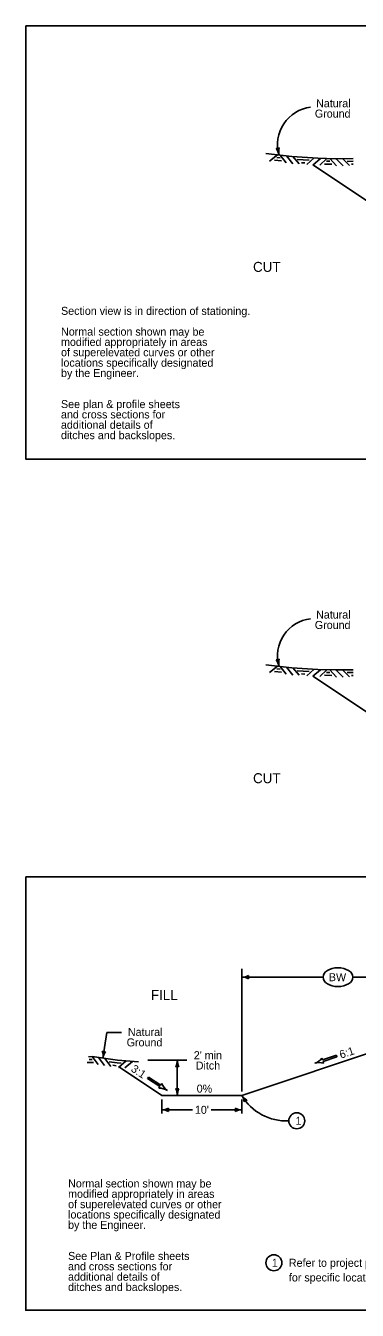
# Model space of a CAD drawing. Extents: x 4574 to 81668, y 5908 to 13780.
# Drawn here: x 10148 to 10645, y 5908 to 7834 of the extents above; entities that cross this region are included whole.
import ezdxf

# ---------------------------------------------------------------- set-up
doc = ezdxf.new("R2010")
doc.units = 0
for name, color, linetype in [('Cell', 7, 'Continuous'), ('dsnStdBorder', 7, 'Continuous'), ('dsnStdLabel', 7, 'Continuous'), ('dsnStdNote', 7, 'Continuous'), ('dsnTextFinalPlan', 7, 'Continuous'), ('dsnXsExistingGround', 7, 'Continuous')]:
    doc.layers.add(name, color=color, linetype=linetype)

msp = doc.modelspace()

# ---------------------------------------------------------------- linework, layer by layer
at = {"layer": 'Cell'}
for p, q in [((10757.5, 7505.6), (10577.8, 7625.3)), ((10757.5, 6738.7), (10577.8, 6858.5)), ((10780.6, 6332.7), (10471.7, 6229.8)), ((10351.7, 6229.8), (10288.2, 6272.1)), ((10351.7, 6229.8), (10471.7, 6229.8))]:
    msp.add_line(p, q, dxfattribs=at)
at = {"layer": 'dsnStdBorder'}
for points in [[(10147.5, 7834), (13252.5, 7834), (13252.5, 7184), (10147.5, 7184), (10147.5, 7834)], [(10147.5, 6557.5), (13252.5, 6557.5), (13252.5, 5907.5), (10147.5, 5907.5), (10147.5, 6557.5)]]:
    msp.add_lwpolyline(points, dxfattribs=at)
at = {"layer": 'dsnStdLabel'}
for p, q in [((10269.3, 6324.2), (10263.1, 6285.8)), ((10291, 6324.2), (10269.3, 6324.2)), ((10591.7, 6285.8), (10592.6, 6283.2)), ((10592.6, 6283.2), (10613.4, 6290.1)), ((10614.2, 6287.9), (10593.3, 6280.9)), ((10593.3, 6280.9), (10594.2, 6278.3)), ((10613.4, 6290.1), (10614.2, 6287.9)), ((10580.8, 6278), (10580.8, 6278)), ((10331.6, 6257.4), (10330.3, 6255.4)), ((10330.3, 6255.4), (10348.6, 6243.2)), ((10349.9, 6245.2), (10331.6, 6257.4)), ((10348.6, 6243.2), (10347, 6240.8)), ((10351.5, 6247.5), (10349.9, 6245.2)), ((10359.9, 6237.1), (10359.9, 6237.1))]:
    msp.add_line(p, q, dxfattribs=at)
for centre, radius, start, end in [((10581.1, 7656), 56, 96.6165, 196.0565), ((10523.9, 7658), 8.21, 263.2989, 298.7656), ((10506.4, 7636.4), 21.3, 11.0323, 39.1047), ((10548.1, 7644.5), 21.3, 162.9598, 191.0323), ((10581.1, 6889.1), 56, 96.6165, 196.0565), ((10523.9, 6891.1), 8.21, 263.2989, 298.7656), ((10506.4, 6869.6), 21.3, 11.0323, 39.1047), ((10548.1, 6877.7), 21.3, 162.9598, 191.0323), ((10266.1, 6303.3), 8.21, 242.6946, 278.1613), ((10242.2, 6289.3), 21.3, 350.428, 18.5005), ((10284.1, 6282.2), 21.3, 142.3555, 170.428), ((10571.7, 6302.1), 25.8, 290.787, 320.817), ((10588, 6253.2), 25.8, 76.053, 106.083), ((10375.1, 6258), 25.8, 203.9305, 233.9606), ((10346.5, 6215.1), 25.8, 58.6646, 88.6946), ((10537.7, 6267.6), 76, 209.8583, 273.1714), ((10489.4, 6241.5), 21.3, 213.5549, 241.6274), ((10454, 6218), 21.3, 5.4824, 33.5549), ((10481.6, 6214.9), 8.21, 105.8215, 141.2882)]:
    msp.add_arc(centre, radius, start, end, dxfattribs=at)
at = {"layer": 'dsnStdNote'}
for centre in [(10553.9, 6191.7), (10519.6, 5978.8)]:
    msp.add_circle(centre, 12, dxfattribs=at)
at = {"layer": 'dsnTextFinalPlan'}
for p, q in [((10471.7, 6235.8), (10471.7, 6419.7)), ((10593.3, 6407.1), (10471.7, 6407.1)), ((10774.3, 6407.1), (10638.1, 6407.1)), ((10389.3, 6282.6), (10330.5, 6282.6)), ((10374.8, 6229.8), (10374.8, 6282.6)), ((10351.7, 6223.7), (10351.7, 6202.6)), ((10471.7, 6223.7), (10471.7, 6202.6)), ((10351.7, 6208.2), (10397.7, 6208.2)), ((10425.7, 6208.2), (10471.7, 6208.2))]:
    msp.add_line(p, q, dxfattribs=at)
for centre, radius, start, end in [((10471.7, 6428.4), 21.3, 270, 298.0725), ((10471.7, 6385.9), 21.3, 61.9275, 90), ((10489.5, 6407.1), 8.21, 162.2666, 197.7334), ((10353.6, 6282.6), 21.3, 331.9275, 0), ((10396.1, 6282.6), 21.3, 180, 208.0725), ((10374.8, 6264.8), 8.21, 72.2666, 107.7334), ((10374.8, 6247.6), 8.21, 252.2666, 287.7334), ((10353.6, 6229.8), 21.3, 0, 28.0725), ((10396.1, 6229.8), 21.3, 151.9275, 180), ((10351.7, 6229.5), 21.3, 270, 298.0725), ((10351.7, 6187), 21.3, 61.9275, 90), ((10369.5, 6208.2), 8.21, 162.2666, 197.7334), ((10453.9, 6208.2), 8.21, 342.2666, 17.7334), ((10471.7, 6229.5), 21.3, 241.9275, 270), ((10471.7, 6187), 21.3, 90, 118.0725)]:
    msp.add_arc(centre, radius, start, end, dxfattribs=at)
msp.add_ellipse((10615.7, 6407.1), major_axis=(-22.4, 0), ratio=0.628754, dxfattribs=at)
at = {"layer": 'dsnXsExistingGround'}
for p, q in [((10524.8, 7640.4), (10513.1, 7631)), ((10528.8, 7640), (10538.2, 7628.3)), ((10538.5, 7638.8), (10547.9, 7627.1)), ((10547.8, 7638), (10557.6, 7626.7)), ((10580.1, 7635.8), (10568.8, 7625.9)), ((10589.4, 7635), (10578.1, 7625.1)), ((10599.2, 7635), (10588.3, 7624.7)), ((10603.3, 7634.9), (10613.5, 7624)), ((10613, 7634.5), (10623.7, 7623.9)), ((10622.3, 7634.7), (10633, 7624.2)), ((10524.8, 6873.6), (10513.1, 6864.2)), ((10528.8, 6873.1), (10538.2, 6861.5)), ((10538.5, 6871.9), (10547.9, 6860.2)), ((10547.8, 6871.1), (10557.6, 6859.8)), ((10580.1, 6868.9), (10568.8, 6859.1)), ((10589.4, 6868.1), (10578.1, 6858.3)), ((10599.2, 6868.2), (10588.3, 6857.9)), ((10603.3, 6868), (10613.5, 6857.1)), ((10613, 6867.6), (10623.7, 6857.1)), ((10622.3, 6867.8), (10633, 6857.3)), ((10247.1, 6288), (10256.1, 6276)), ((10256.7, 6286.5), (10265.7, 6274.5)), ((10266, 6285.4), (10275, 6273.4)), ((10298.2, 6281.7), (10286.8, 6271.9)), ((10307.5, 6280.9), (10296.1, 6271.1))]:
    msp.add_line(p, q, dxfattribs=at)
for points in [[(10638.6, 7634.8), (10612, 7634.6), (10585.5, 7635.4), (10546.4, 7638.1), (10507.5, 7642.3)], [(10531.2, 7631.2), (10520.6, 7632.3)], [(10528.8, 7635.9), (10523.9, 7636.4)], [(10572.7, 7632.2), (10554.7, 7633.4)], [(10603.6, 7630.8), (10598.7, 7630.9)], [(10638.6, 7630.7), (10629.6, 7630.6)], [(10565.8, 7628.3), (10560.9, 7628.6)], [(10606.3, 7626.3), (10595.7, 7626.6)], [(10638.6, 7626.4), (10636.2, 7626.3)], [(10638.6, 6868), (10612, 6867.8), (10585.5, 6868.6), (10546.4, 6871.2), (10507.5, 6875.4)], [(10531.2, 6864.3), (10520.6, 6865.5)], [(10528.8, 6869), (10523.9, 6869.5)], [(10572.7, 6865.3), (10554.7, 6866.6)], [(10565.8, 6861.4), (10560.9, 6861.8)], [(10606.3, 6859.4), (10595.7, 6859.8)], [(10603.6, 6863.9), (10598.7, 6864.1)], [(10638.6, 6863.9), (10629.6, 6863.8)], [(10638.6, 6859.5), (10636.2, 6859.5)], [(10241.8, 6287.9), (10247.4, 6288), (10285.3, 6282.6), (10316.4, 6280.4)], [(10242.6, 6283.8), (10247.1, 6283.8)], [(10239.8, 6279.4), (10246.9, 6279.4), (10249.1, 6279.1)], [(10272.5, 6280.3), (10284.8, 6278.6), (10290.7, 6278.1)], [(10278.4, 6275.1), (10283.3, 6274.4)]]:
    msp.add_lwpolyline(points, dxfattribs=at)

# ---------------------------------------------------------------- texts
at = {"layer": 'dsnStdLabel'}
for s, p in [('Ground', (10581, 7696.2)), ('Natural', (10582.9, 7711.7)), ('Natural', (10582.9, 6944.9)), ('Ground', (10581, 6929.3)), ('Natural', (10300.8, 6318.9)), ('Ground', (10298.9, 6303.3))]:
    msp.add_text(s, height=12, dxfattribs=at).set_placement(p)
for s, height, rotation, p in [('CUT', 15, 0.0415, (10488.4, 7464.8)), ('CUT', 15, 0.0415, (10488.4, 6698)), ('FILL', 15, 359.9586, (10335.2, 6372.9)), ('6:1', 12, 18.435, (10620.2, 6284.8)), ('3:1', 12, 326.3126, (10304.3, 6266.9))]:
    msp.add_text(s, height=height, rotation=rotation, dxfattribs=at).set_placement(p)
at = {"layer": 'dsnStdNote'}
for s, rotation, p in [('Section view is in direction of stationing.', 359.9583, (10200.5, 7400.4)), ('Normal section shown may be', 359.9583, (10200.5, 7369.3)), ('modified appropriately in areas', 359.9583, (10200.5, 7353.8)), ('of superelevated curves or other', 359.9583, (10200.5, 7338.3)), ('locations specifically designated', 359.9583, (10200.5, 7322.7)), ('by the Engineer.', 359.9583, (10200.5, 7307.2)), ('See plan & profile sheets', 359.9583, (10200.4, 7260.6)), ('and cross sections for', 359.9583, (10200.4, 7245.1)), ('additional details of', 359.9583, (10200.4, 7229.6)), ('ditches and backslopes.', 359.9583, (10200.4, 7214)), ('modified appropriately in areas', 359.9583, (10211.1, 6076.3)), ('Normal section shown may be', 359.9583, (10211.1, 6091.8)), ('of superelevated curves or other', 359.9583, (10211.1, 6060.7)), ('locations specifically designated', 359.9583, (10211.1, 6045.2)), ('by the Engineer.', 359.9583, (10211.1, 6029.7)), ('See Plan & Profile sheets', 359.9583, (10211.1, 5983.1)), ('and cross sections for', 359.9583, (10211, 5967.5)), ('1', 359.9591, (10516.5, 5972.8)), ('Refer to project plan and cross sections', 359.9591, (10542.1, 5972.8)), ('additional details of', 359.9583, (10211, 5952)), ('for specific location of foreslope change.', 359.9591, (10542.1, 5950.8)), ('ditches and backslopes.', 359.9583, (10211, 5936.5))]:
    msp.add_text(s, height=12, rotation=rotation, dxfattribs=at).set_placement(p)
msp.add_text('1', height=12, dxfattribs=at).set_placement((10552, 6185.7))
at = {"layer": 'dsnTextFinalPlan'}
for s, p in [('BW', (10602.1, 6401.1)), ("2' min", (10399.5, 6284.1)), ('Ditch', (10402.5, 6268.6)), ('0%', (10403.9, 6234)), ("10'", (10401.2, 6202.2))]:
    msp.add_text(s, height=12, dxfattribs=at).set_placement(p)

doc.saveas('drawing.dxf')
